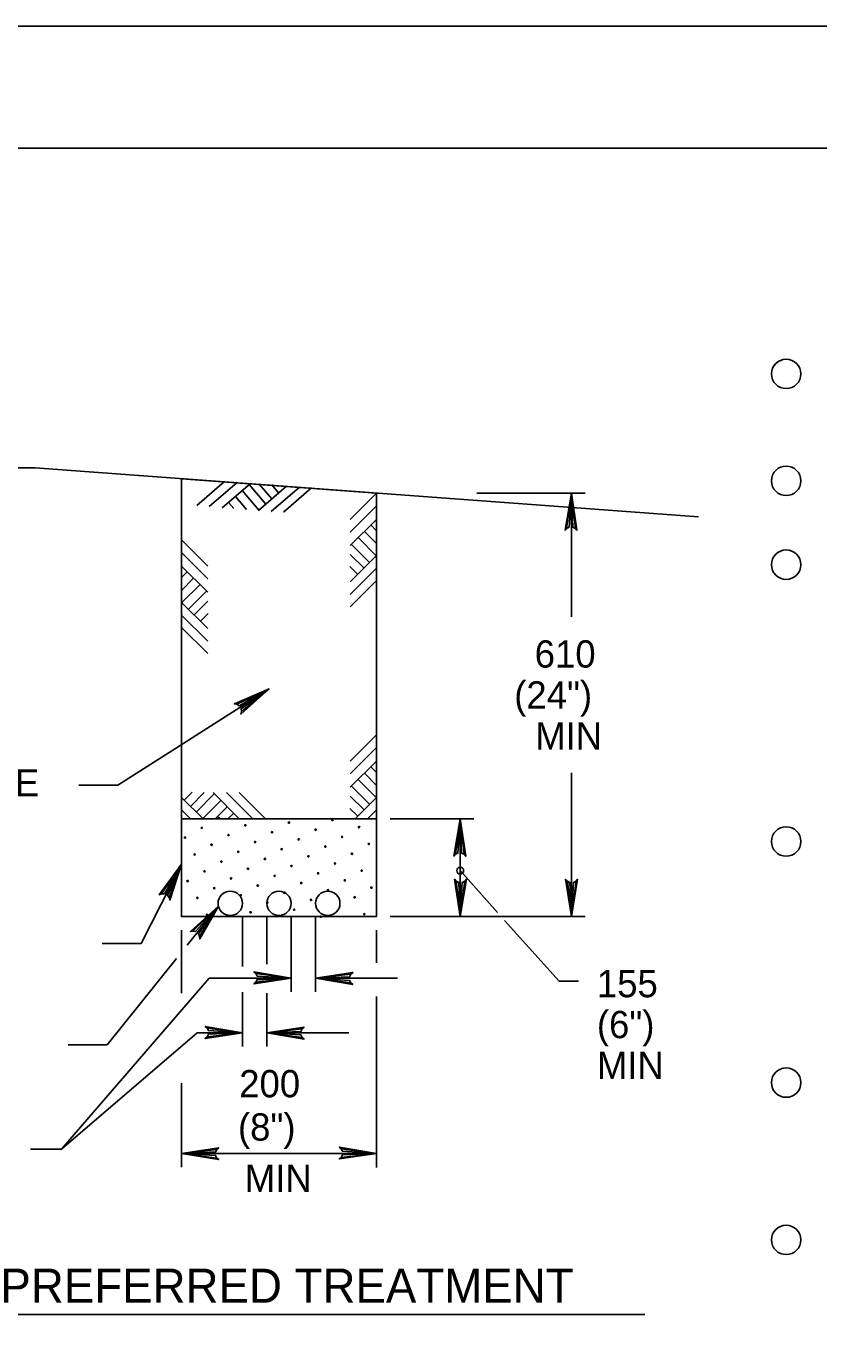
# Model space of a CAD drawing. Extents: x 638448 to 639352, y 297825 to 299013.
# Drawn here: x 638654.5 to 638752, y 298851.5 to 299013.3 of the extents above; entities that cross this region are included whole.
import ezdxf

# ---------------------------------------------------------------- set-up
doc = ezdxf.new("R2010")
doc.units = 0
for name, color, linetype in [('1', 7, 'Continuous'), ('2', 7, 'Continuous'), ('3', 7, 'Continuous'), ('PLT-BNDY', 7, 'Continuous')]:
    doc.layers.add(name, color=color, linetype=linetype)

msp = doc.modelspace()

# ---------------------------------------------------------------- linework, layer by layer
at = {"layer": '1'}
msp.add_lwpolyline([(639272.65, 298434.29), (639272.65, 298998.29), (638486.65, 298998.29), (638486.65, 298434.29), (639272.65, 298434.29), (639272.65, 298460.65), (639072.65, 298460.65), (639072.65, 298525.33), (639272.65, 298525.33), (639272.65, 298554.29), (639072.65, 298554.29), (639072.65, 298434.29), (639151.45, 298434.29), (639151.45, 298460.65), (639151.45, 298434.29), (639228.45, 298434.29), (639228.45, 298460.65), (639228.45, 298448.33), (639272.65, 298448.33)], dxfattribs=at)
for centre in [(638748.04, 298970.5), (638748.04, 298957.34), (638748.04, 298947.02), (638748.04, 298912.95), (638748.04, 298883.27), (638748.04, 298863.91)]:
    msp.add_circle(centre, 1.81, dxfattribs=at)
at = {"layer": '2'}
for p, q in [((638643.81, 298958.93), (638655.64, 298958.93)), ((638655.64, 298958.93), (638737.24, 298952.93)), ((638678.93, 298957.25), (638675.51, 298954.29)), ((638680.48, 298957.13), (638677.06, 298954.18)), ((638682.12, 298957.01), (638678.64, 298954.01)), ((638684.03, 298954.48), (638681.97, 298956.87)), ((638686.58, 298956.68), (638683.13, 298953.7)), ((638684.77, 298955.12), (638683.21, 298956.93)), ((638688.14, 298956.57), (638684.68, 298953.58)), ((638685.6, 298955.84), (638684.71, 298956.87)), ((638681.64, 298953.81), (638680.27, 298955.4)), ((638683.19, 298953.69), (638681.09, 298956.14)), ((638689.64, 298956.46), (638686.19, 298953.49)), ((638694.41, 298952.58), (638697.61, 298955.78)), ((638709.98, 298955.84), (638723.29, 298955.84)), ((638721.61, 298940.61), (638721.61, 298955.84)), ((638680.07, 298953.92), (638679.42, 298954.68)), ((638694.41, 298951.02), (638697.61, 298954.22)), ((638694.41, 298949.38), (638697.66, 298952.63)), ((638697.64, 298951.2), (638696.93, 298951.91)), ((638676.87, 298946.82), (638673.68, 298950.02)), ((638697.64, 298948.07), (638695.36, 298950.35)), ((638697.64, 298949.62), (638696.15, 298951.11)), ((638676.87, 298945.26), (638673.68, 298948.46)), ((638696.79, 298947.29), (638694.56, 298949.52)), ((638676.87, 298943.62), (638673.62, 298946.87)), ((638695.32, 298945.82), (638694.36, 298946.79)), ((638696.1, 298946.6), (638694.41, 298948.29)), ((638694.41, 298944.91), (638697.64, 298948.14)), ((638673.64, 298945.44), (638674.35, 298946.15)), ((638673.64, 298943.86), (638675.13, 298945.35)), ((638694.41, 298943.35), (638697.64, 298946.58)), ((638673.64, 298942.31), (638675.92, 298944.59)), ((638674.49, 298941.53), (638676.72, 298943.76)), ((638694.41, 298941.85), (638697.62, 298945.06)), ((638676.87, 298939.15), (638673.64, 298942.38)), ((638675.18, 298940.84), (638676.87, 298942.53)), ((638676.87, 298937.59), (638673.64, 298940.82)), ((638675.96, 298940.06), (638676.92, 298941.03)), ((638676.87, 298936.09), (638673.66, 298939.3)), ((638694.41, 298922.82), (638697.61, 298926.02)), ((638694.41, 298921.26), (638697.61, 298924.46)), ((638694.41, 298919.62), (638697.66, 298922.87)), ((638697.64, 298919.86), (638696.15, 298921.35)), ((638697.64, 298921.44), (638696.93, 298922.15)), ((638721.61, 298903.73), (638721.61, 298921.39)), ((638696.79, 298917.53), (638694.56, 298919.76)), ((638697.64, 298918.31), (638695.36, 298920.59)), ((638673.64, 298918.38), (638676.29, 298915.73)), ((638673.97, 298918.04), (638674.94, 298919.01)), ((638674.75, 298917.27), (638676.45, 298918.96)), ((638675.44, 298916.57), (638677.67, 298918.8)), ((638676.22, 298915.73), (638678.5, 298918.01)), ((638677.53, 298918.96), (638680.78, 298915.71)), ((638679.18, 298918.96), (638682.37, 298915.76)), ((638680.73, 298918.96), (638683.93, 298915.76)), ((638696.1, 298916.84), (638694.41, 298918.53)), ((638694.99, 298915.73), (638697.64, 298918.38)), ((638674.76, 298915.73), (638673.64, 298916.85)), ((638677.78, 298915.73), (638679.26, 298917.21)), ((638679.35, 298915.73), (638680.06, 298916.44)), ((638695.32, 298916.06), (638694.36, 298917.03)), ((638697.64, 298916.85), (638696.52, 298915.73)), ((638699.32, 298915.73), (638709.6, 298915.73)), ((638707.92, 298915.73), (638707.92, 298903.73)), ((638712.52, 298904.22), (638707.92, 298909.36)), ((638681.14, 298903.66), (638681.14, 298897.57)), ((638684.14, 298903.66), (638684.14, 298897.85)), ((638687.14, 298903.66), (638687.14, 298894.44)), ((638690.14, 298903.66), (638690.14, 298894.44)), ((638699.32, 298903.73), (638709.6, 298903.73)), ((638699.32, 298903.73), (638723.29, 298903.73)), ((638720.09, 298895.74), (638713.39, 298903.24)), ((638673.64, 298902.05), (638673.64, 298894.26)), ((638697.64, 298902.05), (638697.64, 298898.01)), ((638687.14, 298896.12), (638677.06, 298896.12)), ((638690.14, 298896.12), (638700.22, 298896.12)), ((638722.5, 298895.74), (638720.09, 298895.74)), ((638681.14, 298894.41), (638681.14, 298887.72)), ((638684.14, 298894.26), (638684.14, 298887.72)), ((638697.64, 298893.86), (638697.64, 298872.82)), ((638681.14, 298889.4), (638675.57, 298889.4)), ((638684.14, 298889.4), (638694.22, 298889.4)), ((638673.64, 298883.21), (638673.64, 298872.88)), ((638673.64, 298874.56), (638697.64, 298874.56))]:
    msp.add_line(p, q, dxfattribs=at)
for points in [[(638673.64, 298957.6), (638673.64, 298915.73), (638697.64, 298915.73), (638697.64, 298955.84)], [(638673.64, 298915.73), (638673.64, 298957.6), (638697.64, 298955.84)], [(638721.03, 298951.49), (638721.34, 298951.65), (638721.61, 298955.84), (638721.03, 298951.49), (638720.84, 298951.26), (638721.61, 298955.84), (638721.78, 298951.65), (638722.1, 298951.49), (638721.61, 298955.84), (638722.3, 298951.25), (638722.1, 298951.49)], [(638673.64, 298915.73), (638697.64, 298915.73), (638697.64, 298939.73)], [(638673.64, 298915.73), (638697.64, 298915.73), (638697.64, 298939.73)], [(638673.64, 298939.73), (638673.64, 298915.73), (638697.64, 298915.73)], [(638673.64, 298939.73), (638673.64, 298915.73), (638697.64, 298915.73)], [(638661, 298919.88), (638665.8, 298919.88), (638684.41, 298931.72)], [(638680.44, 298929.84), (638680.74, 298929.66), (638684.41, 298931.72), (638680.44, 298929.84), (638680.15, 298929.88), (638684.41, 298931.72), (638680.98, 298929.29), (638681.02, 298928.95), (638684.41, 298931.72), (638680.93, 298928.64), (638681.02, 298928.95)], [(638707.34, 298911.37), (638707.66, 298911.53), (638707.92, 298915.73), (638707.34, 298911.37), (638707.15, 298911.15), (638707.92, 298915.73), (638708.1, 298911.53), (638708.41, 298911.38), (638707.92, 298915.73), (638708.62, 298911.14), (638708.41, 298911.38)], [(638663.89, 298900.41), (638668.69, 298900.41), (638673.64, 298910.15)], [(638671.18, 298906.51), (638671.53, 298906.51), (638673.64, 298910.15), (638671.18, 298906.51), (638670.91, 298906.4), (638673.64, 298910.15), (638671.92, 298906.31), (638672.13, 298906.04), (638673.64, 298910.15), (638672.21, 298905.73), (638672.13, 298906.04)], [(638708.5, 298908.08), (638708.19, 298907.92), (638707.92, 298903.73), (638708.5, 298908.08), (638708.7, 298908.3), (638707.92, 298903.73), (638707.75, 298907.92), (638707.44, 298908.08), (638707.92, 298903.73), (638707.23, 298908.31), (638707.44, 298908.08)], [(638722.19, 298908.08), (638721.87, 298907.92), (638721.61, 298903.73), (638722.19, 298908.08), (638722.38, 298908.3), (638721.61, 298903.73), (638721.43, 298907.92), (638721.12, 298908.08), (638721.61, 298903.73), (638720.91, 298908.31), (638721.12, 298908.08)], [(638674.33, 298900.19), (638678.18, 298904.99)], [(638675.03, 298901.93), (638675.37, 298901.86), (638678.18, 298904.99), (638675.03, 298901.93), (638674.74, 298901.88), (638678.18, 298904.99), (638675.72, 298901.59), (638675.86, 298901.27), (638678.18, 298904.99), (638675.88, 298900.96), (638675.86, 298901.27)], [(638659.68, 298887.93), (638664.48, 298887.93), (638673.01, 298898.55)], [(638682.79, 298896.7), (638682.95, 298896.38), (638687.14, 298896.12), (638682.79, 298896.7), (638682.56, 298896.89), (638687.14, 298896.12), (638682.95, 298895.94), (638682.79, 298895.63), (638687.14, 298896.12), (638682.55, 298895.42), (638682.79, 298895.63)], [(638694.49, 298895.54), (638694.33, 298895.85), (638690.14, 298896.12), (638694.49, 298895.54), (638694.72, 298895.34), (638690.14, 298896.12), (638694.33, 298896.29), (638694.49, 298896.6), (638690.14, 298896.12), (638694.73, 298896.81), (638694.49, 298896.6)], [(638655.08, 298875.07), (638658.86, 298875.07), (638677.06, 298896.12)], [(638676.79, 298889.98), (638676.95, 298889.67), (638681.14, 298889.4), (638676.79, 298889.98), (638676.56, 298890.18), (638681.14, 298889.4), (638676.95, 298889.23), (638676.79, 298888.92), (638681.14, 298889.4), (638676.55, 298888.71), (638676.79, 298888.92)], [(638675.57, 298889.4), (638658.86, 298875.07)], [(638688.49, 298888.82), (638688.33, 298889.14), (638684.14, 298889.4), (638688.49, 298888.82), (638688.72, 298888.63), (638684.14, 298889.4), (638688.33, 298889.58), (638688.49, 298889.89), (638684.14, 298889.4), (638688.73, 298890.1), (638688.49, 298889.89)], [(638677.99, 298873.98), (638677.83, 298874.3), (638673.64, 298874.56), (638677.99, 298873.98), (638678.22, 298873.79), (638673.64, 298874.56), (638677.83, 298874.74), (638677.99, 298875.05), (638673.64, 298874.56), (638678.23, 298875.26), (638677.99, 298875.05)], [(638693.29, 298875.14), (638693.45, 298874.83), (638697.64, 298874.56), (638693.29, 298875.14), (638693.06, 298875.33), (638697.64, 298874.56), (638693.45, 298874.39), (638693.29, 298874.07), (638697.64, 298874.56), (638693.05, 298873.87), (638693.29, 298874.07)]]:
    msp.add_lwpolyline(points, dxfattribs=at)
msp.add_lwpolyline([(638673.64, 298915.73), (638673.64, 298903.73), (638697.64, 298903.73), (638697.64, 298915.73)], close=True, dxfattribs=at)
msp.add_lwpolyline([(638673.64, 298915.73), (638673.64, 298903.73), (638697.64, 298903.73), (638697.64, 298915.73)], close=True, dxfattribs=at)
for centre, radius in [((638676.14, 298914.63), 0.0798), ((638678.22, 298915.83), 0.0798), ((638681.5, 298914.95), 0.0798), ((638686.86, 298915.28), 0.0798), ((638690.14, 298914.4), 0.0798), ((638692.21, 298915.6), 0.0798), ((638695.49, 298914.72), 0.0798), ((638674.07, 298913.43), 0.0798), ((638679.42, 298913.75), 0.0798), ((638682.7, 298912.88), 0.0798), ((638684.78, 298914.08), 0.0798), ((638688.06, 298913.2), 0.0798), ((638693.41, 298913.52), 0.0798), ((638675.27, 298911.35), 0.0798), ((638677.34, 298912.55), 0.0798), ((638680.62, 298911.68), 0.0798), ((638685.98, 298912), 0.0798), ((638689.26, 298911.12), 0.0798), ((638691.34, 298912.32), 0.0798), ((638694.61, 298911.44), 0.0798), ((638696.69, 298912.64), 0.0798), ((638678.54, 298910.48), 0.0798), ((638681.82, 298909.6), 0.0798), ((638683.9, 298910.8), 0.0798), ((638687.18, 298909.92), 0.0798), ((638692.54, 298910.24), 0.0798), ((638707.93, 298909.36), 0.422), ((638674.39, 298908.08), 0.0798), ((638676.47, 298909.28), 0.0798), ((638679.74, 298908.4), 0.0798), ((638685.1, 298908.72), 0.0798), ((638690.46, 298909.04), 0.0798), ((638693.74, 298908.16), 0.0798), ((638695.81, 298909.36), 0.0798), ((638677.67, 298907.2), 0.0798), ((638679.64, 298905.34), 1.5), ((638680.94, 298906.32), 0.0798), ((638683.02, 298907.52), 0.0798), ((638685.64, 298905.34), 1.5), ((638685.64, 298905.34), 1.5), ((638686.3, 298906.64), 0.0798), ((638688.38, 298907.84), 0.0798), ((638691.64, 298905.34), 1.5), ((638691.66, 298906.96), 0.0798), ((638697.01, 298907.28), 0.0798), ((638675.59, 298906), 0.0798), ((638684.22, 298905.44), 0.0798), ((638689.58, 298905.76), 0.0798), ((638694.94, 298906.08), 0.0798), ((638676.79, 298903.92), 0.0798), ((638682.14, 298904.24), 0.0798), ((638687.5, 298904.56), 0.0798), ((638690.78, 298903.68), 0.0798), ((638696.14, 298904), 0.0798)]:
    msp.add_circle(centre, radius, dxfattribs=at)
at = {"layer": '3'}
msp.add_line((638650.55, 298854.72), (638730.67, 298854.72), dxfattribs=at)
at = {"layer": 'PLT-BNDY'}
msp.add_lwpolyline([(638447.65, 299013.29), (639288.65, 299013.29), (639288.65, 298419.29), (638447.65, 298419.29)], close=True, dxfattribs=at)

# ---------------------------------------------------------------- texts
at = {"layer": '3'}
for s, height, p in [('610', 3.36, (638717.1, 298934.35)), ('(24")', 3.36, (638714.58, 298929.31)), ('MIN', 3.36, (638717.16, 298924.27)), ('BROKEN CONCRETE', 3.36, (638610.69, 298918.49)), ('155', 3.36, (638724.75, 298893.78)), ('(6")', 3.36, (638724.75, 298888.74)), ('MIN', 3.36, (638724.75, 298883.7)), ('200', 3.36, (638680.74, 298881.46)), ('(8")', 3.36, (638680.59, 298876.13)), ('MIN', 3.36, (638681.43, 298869.82)), ('PREFERRED TREATMENT', 4.2, (638651.36, 298856.17))]:
    msp.add_text(s, height=height, dxfattribs=at).set_placement(p)

doc.saveas('drawing.dxf')
